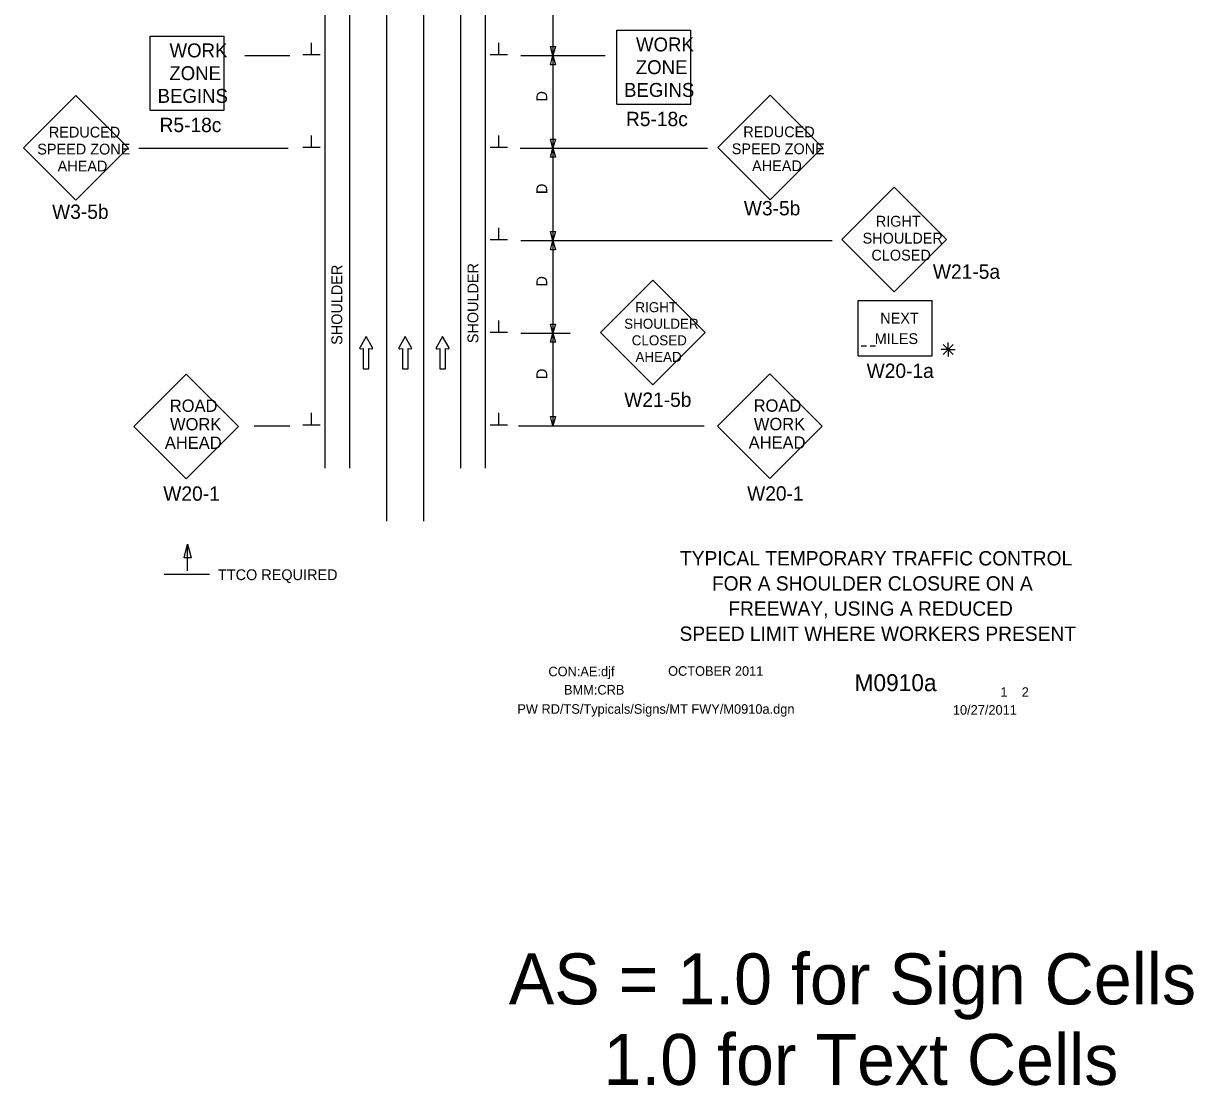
# Model space of a CAD drawing. Extents: x 16730 to 18471, y 6979 to 8225.
# Drawn here: x 16750 to 17509, y 6979 to 7668 of the extents above; entities that cross this region are included whole.
import ezdxf

# ---------------------------------------------------------------- set-up
doc = ezdxf.new("R2010")
doc.units = 0
for name, color, linetype in [('ALI_LEGAL_EX', 7, 'Continuous'), ('BORDER', 7, 'Continuous'), ('BORDER_SIGNAL_WO', 7, 'Continuous'), ('MT_SCRATCH_LEVEL_E', 7, 'Continuous'), ('PAVT_EDGE_EX', 7, 'Continuous'), ('TRAFFIC_SIGNS_PR', 7, 'Continuous'), ('TYPICAL_TEXT_DIMEN_PR', 7, 'Continuous')]:
    doc.layers.add(name, color=color, linetype=linetype)

msp = doc.modelspace()

# ---------------------------------------------------------------- linework, layer by layer
at = {"layer": 'ALI_LEGAL_EX'}
for points in [[(16985.65, 7625.29), (16985.65, 7600.29)], [(17009.65, 7625.29), (17009.65, 7600.29)], [(16985.65, 7525.29), (16985.65, 7500.29)], [(17009.65, 7525.29), (17009.65, 7500.29)], [(16985.65, 7425.29), (16985.65, 7400.29)], [(17009.65, 7425.29), (17009.65, 7400.29)]]:
    msp.add_lwpolyline(points, dxfattribs=at)
at = {"layer": 'MT_SCRATCH_LEVEL_E'}
for p, q in [((16972.46, 7464.59), (16968.34, 7457.35)), ((16972.46, 7464.59), (16968.34, 7457.35)), ((16976.6, 7457.35), (16972.46, 7464.59)), ((16976.6, 7457.35), (16972.46, 7464.59)), ((16997.88, 7464.59), (16993.77, 7457.35)), ((16997.88, 7464.59), (16993.77, 7457.35)), ((17002.03, 7457.35), (16997.88, 7464.59)), ((17002.03, 7457.35), (16997.88, 7464.59)), ((17022.09, 7464.59), (17017.98, 7457.35)), ((17022.09, 7464.59), (17017.98, 7457.35)), ((17026.24, 7457.35), (17022.09, 7464.59)), ((17026.24, 7457.35), (17022.09, 7464.59)), ((16968.83, 7456.67), (16970.6, 7456.99)), ((16968.83, 7456.67), (16970.6, 7456.99)), ((16970.6, 7456.99), (16970.6, 7443.73)), ((16970.6, 7456.99), (16970.6, 7443.73)), ((16974.35, 7443.73), (16974.35, 7456.99)), ((16974.35, 7456.99), (16976.12, 7456.67)), ((16974.35, 7443.73), (16974.35, 7456.99)), ((16974.35, 7456.99), (16976.12, 7456.67)), ((16994.25, 7456.67), (16996.03, 7456.99)), ((16994.25, 7456.67), (16996.03, 7456.99)), ((16996.03, 7456.99), (16996.03, 7443.73)), ((16996.03, 7456.99), (16996.03, 7443.73)), ((16999.77, 7443.73), (16999.77, 7456.99)), ((16999.77, 7456.99), (17001.55, 7456.67)), ((16999.77, 7443.73), (16999.77, 7456.99)), ((16999.77, 7456.99), (17001.55, 7456.67)), ((17018.47, 7456.67), (17020.24, 7456.99)), ((17018.47, 7456.67), (17020.24, 7456.99)), ((17020.24, 7456.99), (17020.24, 7443.73)), ((17020.24, 7456.99), (17020.24, 7443.73)), ((17023.98, 7443.73), (17023.98, 7456.99)), ((17023.98, 7456.99), (17025.76, 7456.67)), ((17023.98, 7443.73), (17023.98, 7456.99)), ((17023.98, 7456.99), (17025.76, 7456.67)), ((16970.6, 7443.73), (16974.35, 7443.73)), ((16970.6, 7443.73), (16974.35, 7443.73)), ((16996.03, 7443.73), (16999.77, 7443.73)), ((16996.03, 7443.73), (16999.77, 7443.73)), ((17020.24, 7443.73), (17023.98, 7443.73)), ((17020.24, 7443.73), (17023.98, 7443.73))]:
    msp.add_line(p, q, dxfattribs=at)
for centre, start, end in [((16968.75, 7457.13), 150.42484, 279.96381), ((16968.75, 7457.13), 150.42484, 279.96381), ((16976.19, 7457.13), 260.03619, 29.77312), ((16976.19, 7457.13), 260.03619, 29.77312), ((16994.18, 7457.13), 150.42484, 279.96381), ((16994.18, 7457.13), 150.42484, 279.96381), ((17001.62, 7457.13), 260.03619, 29.77312), ((17001.62, 7457.13), 260.03619, 29.77312), ((17018.39, 7457.13), 150.42484, 279.96381), ((17018.39, 7457.13), 150.42484, 279.96381), ((17025.83, 7457.13), 260.03619, 29.77312), ((17025.83, 7457.13), 260.03619, 29.77312)]:
    msp.add_arc(centre, 0.463, start, end, dxfattribs=at)
at = {"layer": 'PAVT_EDGE_EX'}
for p, q in [((16985.65, 8211.96), (16985.65, 7344.79)), ((17009.65, 8211.96), (17009.65, 7344.79)), ((16985.65, 8097.28), (16985.65, 7344.79)), ((17009.65, 8097.28), (17009.65, 7344.79)), ((16945.65, 7942.5), (16945.65, 7379.34)), ((16961.65, 7942.41), (16961.65, 7379.34)), ((17033.65, 7942.16), (17033.65, 7379.34)), ((17049.65, 7942.41), (17049.65, 7379.34))]:
    msp.add_line(p, q, dxfattribs=at)
at = {"layer": 'TRAFFIC_SIGNS_PR'}
for p, q in [((17134.97, 7615.39), (17134.97, 7663.39)), ((17134.97, 7663.39), (17182.97, 7663.39)), ((17182.97, 7615.39), (17182.97, 7663.39)), ((16832.54, 7611.53), (16832.54, 7659.53)), ((16832.54, 7659.53), (16880.54, 7659.53)), ((16880.54, 7611.53), (16880.54, 7659.53)), ((16784.23, 7621.02), (16750.29, 7587.08)), ((16818.17, 7587.08), (16784.23, 7621.02)), ((17234.49, 7621.23), (17200.54, 7587.29)), ((17268.43, 7587.29), (17234.49, 7621.23)), ((16832.54, 7611.53), (16880.54, 7611.53)), ((17134.97, 7615.39), (17182.97, 7615.39)), ((16750.29, 7587.08), (16784.23, 7553.14)), ((16784.23, 7553.14), (16818.17, 7587.08)), ((17200.54, 7587.29), (17234.49, 7553.35)), ((17234.49, 7553.35), (17268.43, 7587.29)), ((17314.93, 7561.43), (17280.99, 7527.48)), ((17348.87, 7527.48), (17314.93, 7561.43)), ((17280.99, 7527.48), (17314.93, 7493.54)), ((17314.93, 7493.54), (17348.87, 7527.48)), ((17158.42, 7501.21), (17124.48, 7467.27)), ((17192.36, 7467.27), (17158.42, 7501.21)), ((17291.58, 7452.07), (17291.58, 7488.07)), ((17291.58, 7488.07), (17339.58, 7488.07)), ((17339.58, 7452.07), (17339.58, 7488.07)), ((17124.48, 7467.27), (17158.42, 7433.33)), ((17158.42, 7433.33), (17192.36, 7467.27)), ((17293.44, 7458.67), (17296.94, 7458.67)), ((17299.24, 7458.67), (17302.74, 7458.67)), ((17291.58, 7452.07), (17339.58, 7452.07)), ((16855.78, 7440.31), (16821.84, 7406.37)), ((16889.72, 7406.37), (16855.78, 7440.31)), ((17234.32, 7440.4), (17200.38, 7406.45)), ((17268.26, 7406.45), (17234.32, 7440.4)), ((16821.84, 7406.37), (16855.78, 7372.42)), ((16855.78, 7372.42), (16889.72, 7406.37)), ((17200.38, 7406.45), (17234.32, 7372.51)), ((17234.32, 7372.51), (17268.26, 7406.45))]:
    msp.add_line(p, q, dxfattribs=at)
at = {"layer": 'TYPICAL_TEXT_DIMEN_PR'}
for p, q in [((17093.65, 7706.83), (17093.65, 7646.83)), ((16937.02, 7647.26), (16937.02, 7655.05)), ((17058.58, 7647.26), (17058.58, 7655.05)), ((17093.65, 7646.83), (17092.08, 7652.7)), ((17092.08, 7652.7), (17093.65, 7652.7)), ((17093.65, 7652.7), (17095.22, 7652.7)), ((17095.22, 7652.7), (17093.65, 7646.83)), ((16893.76, 7646.83), (16923.12, 7646.83)), ((16942.65, 7647.26), (16931.4, 7647.26)), ((17064.21, 7647.26), (17052.96, 7647.26)), ((17072.81, 7646.83), (17127.44, 7646.83)), ((17092.08, 7640.97), (17093.65, 7646.83)), ((17093.65, 7640.97), (17092.08, 7640.97)), ((17093.65, 7646.83), (17093.65, 7586.83)), ((17093.65, 7646.83), (17095.22, 7640.97)), ((17095.22, 7640.97), (17093.65, 7640.97)), ((16937.02, 7587.26), (16937.02, 7595.05)), ((17058.58, 7587.26), (17058.58, 7595.05)), ((17093.65, 7586.83), (17092.08, 7592.7)), ((17092.08, 7592.7), (17093.65, 7592.7)), ((17093.65, 7592.7), (17095.22, 7592.7)), ((17095.22, 7592.7), (17093.65, 7586.83)), ((16825.15, 7586.83), (16921.99, 7586.83)), ((16942.65, 7587.26), (16931.4, 7587.26)), ((17064.21, 7587.26), (17052.96, 7587.26)), ((17072.33, 7586.83), (17193.8, 7586.83)), ((17092.08, 7580.97), (17093.65, 7586.83)), ((17093.65, 7580.97), (17092.08, 7580.97)), ((17093.65, 7586.83), (17093.65, 7526.83)), ((17093.65, 7586.83), (17095.22, 7580.97)), ((17095.22, 7580.97), (17093.65, 7580.97)), ((17058.58, 7527.26), (17058.58, 7535.05)), ((17064.21, 7527.26), (17052.96, 7527.26)), ((17072.81, 7526.83), (17274.57, 7526.83)), ((17093.65, 7526.83), (17092.08, 7532.7)), ((17092.08, 7532.7), (17093.65, 7532.7)), ((17092.08, 7520.97), (17093.65, 7526.83)), ((17093.65, 7532.7), (17095.22, 7532.7)), ((17095.22, 7532.7), (17093.65, 7526.83)), ((17093.65, 7526.83), (17093.65, 7466.83)), ((17093.65, 7526.83), (17095.22, 7520.97)), ((17093.65, 7520.97), (17092.08, 7520.97)), ((17095.22, 7520.97), (17093.65, 7520.97)), ((17058.58, 7467.26), (17058.58, 7475.05)), ((17064.21, 7467.26), (17052.96, 7467.26)), ((17072.81, 7466.83), (17104.89, 7466.83)), ((17093.65, 7466.83), (17092.08, 7472.7)), ((17092.08, 7472.7), (17093.65, 7472.7)), ((17092.08, 7460.97), (17093.65, 7466.83)), ((17093.65, 7472.7), (17095.22, 7472.7)), ((17095.22, 7472.7), (17093.65, 7466.83)), ((17093.65, 7466.83), (17093.65, 7406.83)), ((17093.65, 7466.83), (17095.22, 7460.97)), ((17093.65, 7460.97), (17092.08, 7460.97)), ((17095.22, 7460.97), (17093.65, 7460.97)), ((17353.05, 7459.41), (17346.67, 7453.03)), ((17346.68, 7459.41), (17353.05, 7453.03)), ((17349.86, 7456.22), (17349.86, 7460.67)), ((17349.86, 7456.22), (17345.33, 7456.22)), ((17349.86, 7456.22), (17353.05, 7456.22)), ((17349.86, 7456.22), (17354.34, 7456.22)), ((17349.86, 7456.22), (17349.86, 7451.72)), ((16937.02, 7407.26), (16937.02, 7415.05)), ((17058.58, 7407.26), (17058.58, 7415.05)), ((16899.92, 7406.83), (16923.12, 7406.83)), ((16942.65, 7407.26), (16931.4, 7407.26)), ((17064.21, 7407.26), (17052.96, 7407.26)), ((17071.2, 7406.83), (17191.58, 7406.83)), ((17093.65, 7406.83), (17092.08, 7412.7)), ((17092.08, 7412.7), (17093.65, 7412.7)), ((17093.65, 7412.7), (17095.22, 7412.7)), ((17095.22, 7412.7), (17093.65, 7406.83)), ((16854.42, 7321.08), (16856.77, 7329.88)), ((16856.77, 7312.75), (16856.77, 7329.88)), ((16856.77, 7329.88), (16859.13, 7321.08)), ((16856.77, 7321.08), (16854.42, 7321.08)), ((16859.13, 7321.08), (16856.77, 7321.08)), ((16870.95, 7310.25), (16841.51, 7310.25))]:
    msp.add_line(p, q, dxfattribs=at)

# ---------------------------------------------------------------- texts
at = {"layer": 'BORDER'}
for s, p in [('TYPICAL TEMPORARY TRAFFIC CONTROL', (17176.01, 7316.16)), ('FOR A SHOULDER CLOSURE ON A', (17196.72, 7299.86)), ('FREEWAY, USING A REDUCED', (17207.33, 7283.56)), ('SPEED LIMIT WHERE WORKERS PRESENT', (17175.72, 7267.26))]:
    msp.add_text(s, height=9.3, dxfattribs=at).set_placement(p)
at = {"layer": 'BORDER_SIGNAL_WO'}
for s, height, p in [('CON:AE:djf', 6.2, (17090.69, 7244.31)), ('    OCTOBER 2011    ', 6.2, (17159.08, 7244.59)), ('BMM:CRB   ', 6.2, (17100.81, 7232.42)), ('    M0910a   ', 11, (17272.86, 7234.63)), (' 1    2 ', 6.2, (17381.45, 7230.95)), ('PW RD/TS/Typicals/Signs/MT FWY/M0910a.dgn    ', 6.2, (17070.55, 7219.96)), ('10/27/2011', 6.2, (17352.93, 7219.38)), ('AS = 1.0 for Sign Cells', 33.0301, (17065.02, 7031.48)), ('     1.0 for Text Cells', 33.0301, (17065.02, 6979.25))]:
    msp.add_text(s, height=height, dxfattribs=at).set_placement(p)
at = {"layer": 'TRAFFIC_SIGNS_PR'}
for s, height, p in [('WORK', 9.021, (17147.48, 7649.6)), ('WORK', 9.021, (16845.04, 7645.73)), ('ZONE', 9.021, (17147.33, 7634.84)), ('ZONE', 9.021, (16844.9, 7630.97)), ('BEGINS', 9.021, (16837.31, 7616.21)), ('BEGINS', 9.021, (17139.74, 7620.08)), ('R5-18c', 9.3, (17140.99, 7601.1)), ('R5-18c', 9.3, (16838.56, 7597.23)), ('REDUCED', 7, (16766.8, 7593.72)), ('REDUCED', 7, (17217.06, 7593.92)), ('SPEED ZONE', 7, (16759.29, 7582.72)), ('SPEED ZONE', 7, (17209.55, 7582.92)), ('AHEAD', 7, (16772.49, 7571.72)), ('AHEAD', 7, (17222.75, 7571.92)), ('W3-5b', 9.3, (16768.88, 7540.98)), ('W3-5b', 9.3, (17217.41, 7543.25)), ('RIGHT', 7, (17302.98, 7535.94)), ('SHOULDER', 7, (17294.41, 7524.94)), ('CLOSED', 7, (17300.12, 7513.94)), ('W21-5a', 9.3, (17339.99, 7502.1)), ('RIGHT', 6.5, (17147.09, 7480.44)), ('SHOULDER', 6.5, (17139.82, 7469.69)), ('NEXT', 7, (17305.84, 7473.08)), ('   MILES', 7, (17294.5, 7459.78)), ('CLOSED', 6.5, (17144.71, 7458.94)), ('AHEAD', 6.5, (17147.16, 7448.19)), ('W20-1a', 9.3, (17297.01, 7437.77)), ('W21-5b', 9.3, (17139.86, 7419.03)), ('ROAD', 8, (16845.21, 7415.79)), ('ROAD', 8, (17223.75, 7415.88)), ('WORK', 8, (16845.34, 7403.79)), ('WORK', 8, (17223.88, 7403.88)), ('AHEAD', 8, (16841.98, 7391.79)), ('AHEAD', 8, (17220.52, 7391.88)), ('W20-1', 9.3, (16840.99, 7358.13)), ('W20-1', 9.3, (17219.53, 7358.22))]:
    msp.add_text(s, height=height, dxfattribs=at).set_placement(p)
at = {"layer": 'TYPICAL_TEXT_DIMEN_PR'}
for s, p in [('D', (17089.92, 7617.08)), ('D', (17089.92, 7557.08)), ('SHOULDER', (17045.24, 7460.3)), ('SHOULDER', (16957.01, 7459.24)), ('D', (17089.92, 7497.08)), ('D', (17089.92, 7437.08))]:
    msp.add_text(s, height=7, rotation=90, dxfattribs=at).set_placement(p)
msp.add_text('TTCO REQUIRED', height=7, dxfattribs=at).set_placement((16876.46, 7306.65))

doc.saveas('drawing.dxf')
